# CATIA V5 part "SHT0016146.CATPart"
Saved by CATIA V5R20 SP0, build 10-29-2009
Part number: SHT0016146
Bounding box of the stored display mesh (mm): x -141.9 to 25.758, y -864.5 to -593.501, z 15.9 to 106.4
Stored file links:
  F:\福田A6\1-数据\6-冻结数据\第九批\设变\静电导线设变\SHT0016014-宽车主驾驶底部支架焊接总成\更改后数据\SHT0016146-宽车主驾驶后侧钣金\SHT0016146.CATPart

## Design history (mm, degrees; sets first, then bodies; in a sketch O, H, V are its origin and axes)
Set1
  DatumSurface1
  DatumSurface2
  DatumCurve1
  DatumSurface3
  DatumCurve2 to DatumCurve9
Body1 (main body)
Body2 "SHT0016146-宽车主驾驶后侧钣金"
  Solid1: solid without history
  Sketch1 on face of DatumSurface2, origin (0, 0, 106.4), H (1, 0, 0), V (0, 1, 0)
    circle A1 centre (-59, -676.0026) radius 4.5
    reference projected arc E1 centre (-59, -676.0026) radius 4.5 from (-62.9491, -673.8452) to (-55.0509, -678.1601) ccw from edge of DatumCurve1
    radius A1 = 4.5
    concentricity: A1 E1
  Pocket1: profile Sketch1, direction (0, 0, -1), length 20
  Sketch2 on face of DatumSurface3, origin (0, 0, 46.25), H (1, 0, 0), V (0, 1, 0)
    arc A1 centre (-32.8163, -807.0209) radius 3.5 from (-29.654, -805.5211) to (-29.6542, -808.5211) ccw
    reference projected arc E1 centre (-32.8163, -807.0209) radius 3.5 from (-29.7448, -805.3429) to (-35.8879, -808.6989) ccw from edge of DatumCurve2
    point P2 (-26.3161, -805.5211)
    point P3 (-26.3161, -808.5211)
    point P4 (-26.3161, -805.5211)
    point P5 (-26.3161, -808.5211)
    line L1 (-26.3161, -808.5211) -> (-26.3161, -805.5211)
    line L2 (-26.3161, -808.5211) -> (-29.6542, -808.5211)
    line L3 (-29.654, -805.5211) -> (-26.3161, -805.5211)
    radius A1 = 3.5
    concentricity: A1 E1
    coincidence: P2 P4, P3 P5
  Pocket2: profile Sketch2, direction (0, 0, -1), length 20
  Sketch3 on face of Solid1, origin (0, 0, 46.25), H (1, 0, 0), V (0, 1, 0)
    arc A1 centre (-32.8163, -650.9801) radius 3.5 from (-29.6541, -649.4799) to (-29.654, -652.4799) ccw
    reference projected arc E1 centre (-32.8163, -650.9801) radius 3.5 from (-35.8879, -652.6581) to (-29.657, -652.4863) ccw from edge of DatumCurve6
    line L1 (-26.3161, -652.4799) -> (-29.654, -652.4799)
    line L2 (-26.3161, -652.4799) -> (-26.3161, -649.4799)
    line L3 (-29.6541, -649.4799) -> (-26.3161, -649.4799)
    point P8 (-29.654, -652.4799)
    point P9 (-29.6541, -649.4799)
    radius A1 = 3.5
    concentricity: A1 E1
    coincidence: L1 P8, L3 P9
  Pocket3: profile Sketch3, direction (0, 0, -1), length 20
